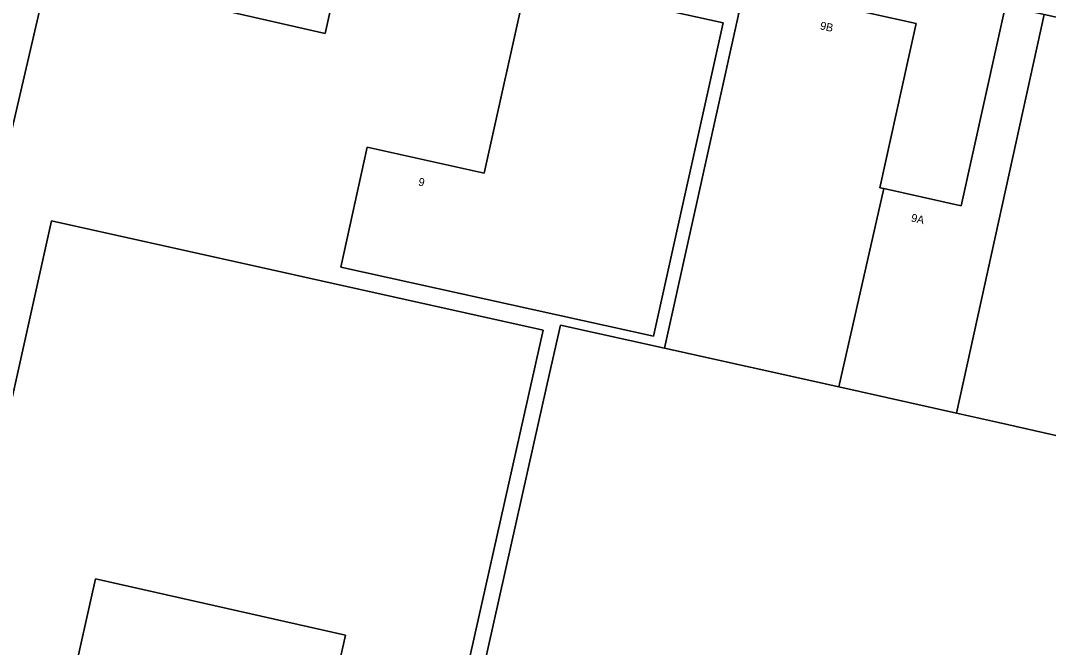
# Model space of a CAD drawing. Extents: x 162172 to 163187, y 382874 to 383685.
# Drawn here: x 162933.9 to 163062.4, y 382971.9 to 383050.2 of the extents above; entities that cross this region are included whole.
import ezdxf

# ---------------------------------------------------------------- set-up
doc = ezdxf.new("R2010")
doc.units = 0
for name, color, linetype in [('IMGEO_Erf', 7, 'Continuous'), ('IMGEO_Hek', 7, 'Continuous'), ('IMGEO_Pand', 7, 'Continuous'), ('IMGEO_Pand_nummerreeks', 7, 'Continuous'), ('IMGEO_Voetpad_halfverhard', 7, 'Continuous')]:
    doc.layers.add(name, color=color, linetype=linetype)

msp = doc.modelspace()

# ---------------------------------------------------------------- linework, layer by layer
at = {"layer": 'IMGEO_Erf'}
for points in [[(163102.74, 383047.26), (163100.9, 383047.66), (163090.56, 383049.91), (163088.21, 383050.42), (163083.55, 383051.44), (163068.1, 383054.83), (163062.95, 383055.97), (163057.94, 383057.07), (163048.33, 383059.19), (163036.52, 383061.81), (163026.73, 383063.97), (163002.59, 383069.27), (163000.92, 383069.64), (162977.74, 383074.75), (162971.96, 383048.6), (162942.63, 383055.33), (162944.67, 383064.64), (162947.28, 383076.56), (162948.23, 383080.89), (162947.57, 383081.03), (162947.65, 383081.35), (162942.93, 383082.39), (162889.98, 383094.11)], [(163023.65, 383051.15), (163000, 383056.45), (162998.13, 383056.87), (162999.85, 383064.73), (163000, 383064.7), (163025.43, 383059.14), (163024.43, 383054.61), (163024.87, 383054.52), (163045.83, 383049.86), (163044.75, 383044.98), (163041.28, 383029.34), (163041.8, 383029.22), (163051.43, 383027.09), (163055.89, 383047.19), (163056.98, 383052.07), (163061.84, 383050.99), (163070.65, 383049.03), (163070.02, 383046.11), (163073.53, 383045.33)], [(162989.5, 382959.23), (162998.63, 383000), (163000, 383006.13), (163001.36, 383012.18), (163014.36, 383009.3), (163023.65, 383051.15)], [(162921.78, 382953.42), (162937.75, 383025.21), (162999.19, 383011.55), (162985.81, 382951.75)], [(162970.44, 382955.19), (162974.52, 382973.44), (162943.27, 382980.46), (162937.82, 382956.09)]]:
    msp.add_lwpolyline(points, dxfattribs=at)
for points in [[(162930.37, 383026.33), (162915.89, 383029.5), (162883.16, 383036.67), (162865.2, 383040.6), (162863.57, 383033.17), (162842.07, 383038.01), (162843.71, 383045.3), (162852.66, 383085.03), (162873.9, 383080.35), (162905.02, 383073.48), (162905.85, 383077.13), (162916.54, 383074.78), (162915.72, 383071.12), (162939.59, 383065.83)], [(162997.19, 383055.34), (163021.69, 383049.92), (163013, 383010.79), (162973.91, 383019.4), (162977.21, 383034.39), (162991.82, 383031.15)]]:
    msp.add_lwpolyline(points, close=True, dxfattribs=at)
at = {"layer": 'IMGEO_Hek'}
msp.add_lwpolyline([(162977.74, 383074.75), (162971.96, 383048.6), (162942.63, 383055.33), (162944.67, 383064.64)], dxfattribs=at)
at = {"layer": 'IMGEO_Pand'}
for points in [[(162939.59, 383065.83), (162915.72, 383071.12), (162916.54, 383074.78), (162905.85, 383077.13), (162905.02, 383073.48), (162873.9, 383080.35), (162865.2, 383040.6), (162883.16, 383036.67), (162915.89, 383029.5), (162930.37, 383026.33)], [(163013, 383010.79), (163021.69, 383049.92), (162997.19, 383055.34), (162991.82, 383031.15), (162977.21, 383034.39), (162973.91, 383019.4)], [(163044.75, 383044.98), (163045.83, 383049.86), (163024.87, 383054.52), (163024.43, 383054.61), (163023.65, 383051.15), (163014.36, 383009.3), (163036.16, 383004.44), (163041.8, 383029.22), (163041.28, 383029.34)], [(163050.85, 383001.17), (163061.84, 383050.99), (163056.98, 383052.07), (163055.89, 383047.19), (163051.43, 383027.09), (163041.8, 383029.22), (163036.16, 383004.44)], [(162936.37, 382950.07), (162937.82, 382956.09), (162943.27, 382980.46), (162974.52, 382973.44), (162970.44, 382955.19), (162985.81, 382951.75), (162999.19, 383011.55), (162937.75, 383025.21), (162921.78, 382953.42)]]:
    msp.add_lwpolyline(points, close=True, dxfattribs=at)
for points in [[(163073.53, 383045.33), (163070.02, 383046.11), (163070.65, 383049.03), (163061.84, 383050.99), (163050.85, 383001.17), (163056.12, 383000), (163090.91, 382992.11), (163092.68, 383000), (163095.78, 383013.83), (163090.38, 383015.04), (163088.91, 383015.36), (163092.19, 383030.47)], [(163090.91, 382992.11), (163056.12, 383000), (163050.85, 383001.17), (163036.16, 383004.44), (163014.36, 383009.3), (163001.36, 383012.18), (163000, 383006.13), (162998.63, 383000), (162989.5, 382959.23), (162988.4, 382954.32), (162997.44, 382952.3), (162995.86, 382945.26), (162989.57, 382946.67), (162987.75, 382938.55), (162993.86, 382937.18), (162994.32, 382937.08), (163000, 382935.81), (163022.2, 382930.83), (163048.34, 382924.97), (163054.02, 382923.69), (163066.78, 382920.83)]]:
    msp.add_lwpolyline(points, dxfattribs=at)
at = {"layer": 'IMGEO_Voetpad_halfverhard'}
msp.add_lwpolyline([(162944.67, 383064.64), (162942.63, 383055.33), (162971.96, 383048.6), (162977.74, 383074.75)], dxfattribs=at)

# ---------------------------------------------------------------- texts
at = {"layer": 'IMGEO_Pand_nummerreeks'}
for s, rotation, p in [('9B', 347.4694, (163033.74, 383049.14)), ('9', 347.5044, (162983.54, 383029.63)), ('9A', 347.4788, (163045.12, 383025.13))]:
    msp.add_text(s, height=1, rotation=rotation, dxfattribs=at).set_placement(p)

doc.saveas('drawing.dxf')
